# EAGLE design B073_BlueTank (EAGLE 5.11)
COMPANY: CuBeatSystems; COPYRIGHT: Shinichiro Nakamura; PROJECT_NAME: BlueTank ACB-BF592; PROJECT_NUMBER: B073; PROJECT_VERSION: 1.0.0
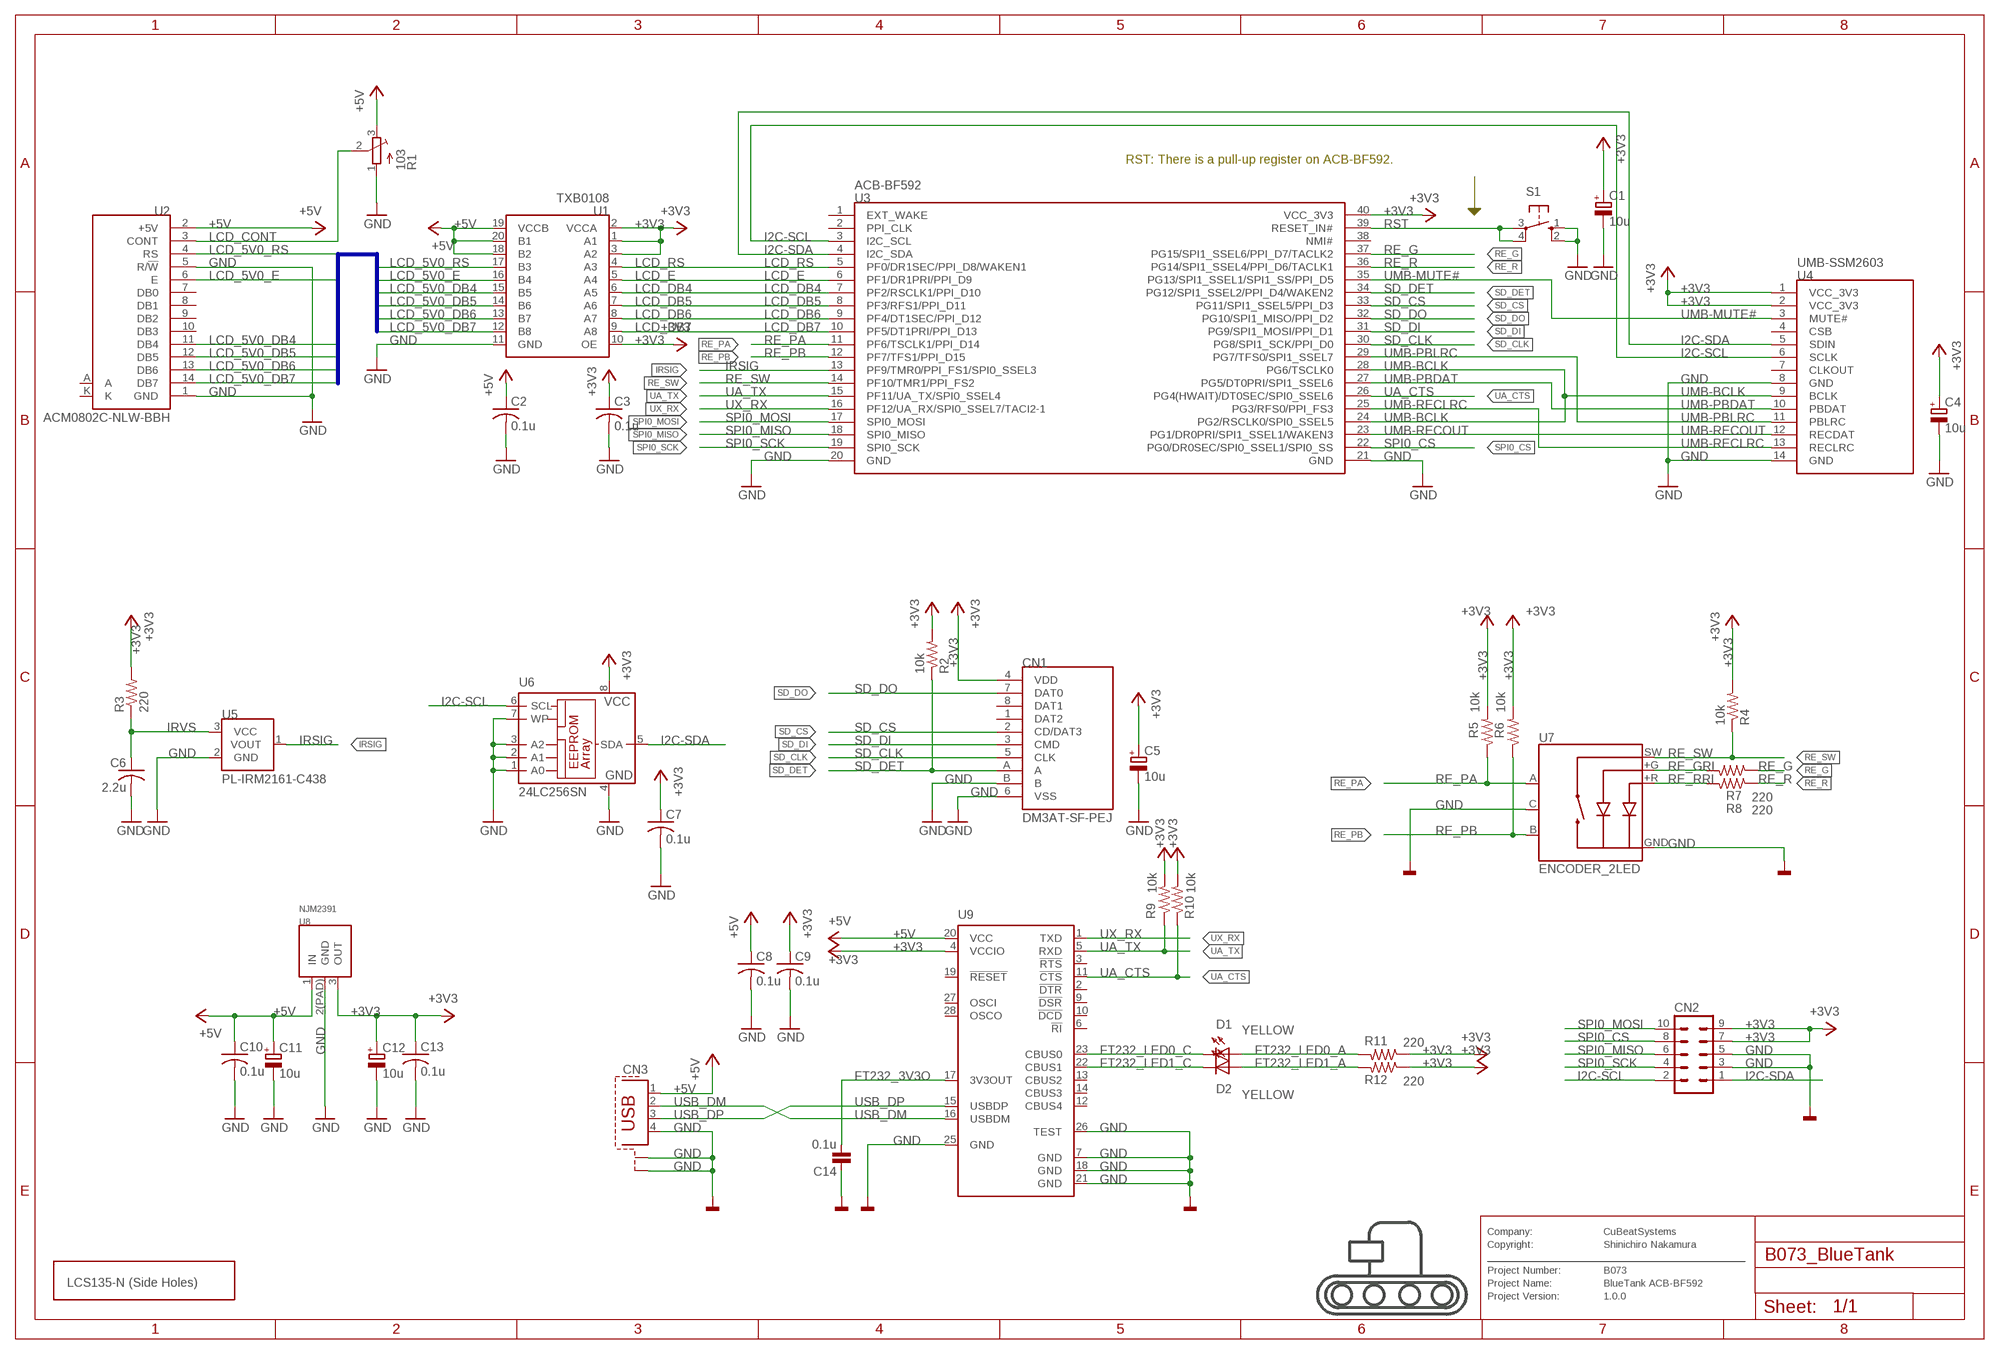
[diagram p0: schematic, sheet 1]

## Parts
C1  10u  CPOL-EUB  [PANASONIC_B]
C2  0.1u  C-USC0805  [C0805]
C3  0.1u  C-USC0805  [C0805]
C4  10u  CPOL-EUB  [PANASONIC_B]
C5  10u  CPOL-EUB  [PANASONIC_B]
C6  2.2u  C-USC0805  [C0805]
C7  0.1u  C-USC0805  [C0805]
C8  0.1u  C-USC0805  [C0805]
C9  0.1u  C-USC0805  [C0805]
C10  0.1u  C-USC0805  [C0805]
C11  10u  CPOL-EUB  [PANASONIC_B]
C12  10u  CPOL-EUB  [PANASONIC_B]
C13  0.1u  C-USC0805  [C0805]
C14  0.1u  C0603  [0603]
CN1  DM3AT-SF-PEJ  [DM3AT-SF-PEJ]
CN2  ML10L  [ML10L]
CN3  PN61729-S  [PN61729-S]
D1  YELLOW  LED_0805  [LED_0805]
D2  YELLOW  LED_0805  [LED_0805]
R1  103  TRIM_EU-SM-42/43A  [SM-42/43A]
R2  10k  R-US_M0805  [M0805]
R3  220  R-US_M0805  [M0805]
R4  10k  R-US_M0805  [M0805]
R5  10k  R-US_M0805  [M0805]
R6  10k  R-US_M0805  [M0805]
R7  220  R-US_M0805  [M0805]
R8  220  R-US_M0805  [M0805]
R9  10k  R-US_M0805  [M0805]
R10  10k  R-US_M0805  [M0805]
R11  220  R-US_M0805  [M0805]
R12  220  R-US_M0805  [M0805]
S1  10-XX  [B3F-10XX]
U1  TXB0108  [PW_R-PDSO-G20]
U2  ACM0802C-NLW-BBH  [ACM0802C-NLW-BBH]
U3  ACB-BF592  [ACB-BF592]
U4  UMB-SSM2603  [UMB-SSM2603]
U5  PL-IRM2161-C438  PL-IRM2121-A538  [PL-IRM2121-A538]
U6  24LC256SN  [SO-08]
U7  ENCODER_2LED  [ENCODER_LED_2]
U8  NJM2391  TA48M033F  [HSIP3-P-2.30B]
U9  FT232RL  [SSOP28]
V  LCS135-N-SIDE-HOLES  [LCS-135-N-SIDE-HOLES]

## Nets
+3V3: C1.+ C3.1 C4.+ C5.+ C7.1 C9.1 C12.+ C13.1 CN1.4(VDD) CN2.7 CN2.9 R2.2 R3.2 R4.2 R5.2 R6.2 R9.2 R10.2 R11.1 R12.1 U1.1(A1) U1.2(VCCA) U1.3(A2) U1.10(OE) U3.40(VCC_3V3) U4.1(VCC_3V3) U4.2(VCC_3V3) U6.8(VCC) U8.3(OUT) U9.4(VCCIO)
+5V [PWR]: C2.1 C8.1 C10.1 C11.+ CN3.1 R1.3(E) U1.18(B2) U1.19(VCCB) U1.20(B1) U2.2(+5V) U8.1(IN) U9.20(VCC)
FT232_3V3O: C14.2 U9.17(3V3OUT)
FT232_LED0_A: D1.A R11.2
FT232_LED0_C: D1.K U9.23(CBUS0)
FT232_LED1_A: D2.A R12.2
FT232_LED1_C: D2.K U9.22(CBUS1)
GND: C1.- C2.2 C3.2 C4.- C5.- C6.2 C7.2 C8.2 C9.2 C10.2 C11.- C12.- C13.2 C14.1 CN1.6(VSS) CN1.B CN2.3 CN2.5 CN3.4 CN3.S1 CN3.S2 R1.1(A) S1.1(S) S1.2(S1) U1.11(GND) U2.1(GND) U2.5(R/!W) U3.20(GND) U3.21(GND) U4.8(GND) U4.14(GND) U5.2(GND) U6.1(A0) U6.2(A1) U6.3(A2) U6.4(GND) U6.7(WP) U7.C U7.GND(-) U8.2(PAD)(GND) U9.7(GND) U9.18(GND) U9.21(GND) U9.25(GND) U9.26(TEST)
I2C-SCL: CN2.2 U3.3(I2C_SCL) U4.6(SCLK) U6.6(SCL)
I2C-SDA: CN2.1 U3.4(I2C_SDA) U4.5(SDIN) U6.5(SDA)
IRSIG: U3.13(PF9/TMR0/PPI_FS1/SPI0_SSEL3) U5.1(VOUT)
IRVS: C6.1 R3.1 U5.3(VCC)
LCD_5V0_DB4: U1.15(B5) U2.11(DB4)
LCD_5V0_DB5: U1.14(B6) U2.12(DB5)
LCD_5V0_DB6: U1.13(B7) U2.13(DB6)
LCD_5V0_DB7: U1.12(B8) U2.14(DB7)
LCD_5V0_E: U1.16(B4) U2.6(E)
LCD_5V0_RS: U1.17(B3) U2.4(RS)
LCD_CONT: R1.2(S) U2.3(CONT)
LCD_DB4: U1.6(A5) U3.7(PF2/RSCLK1/PPI_D10)
LCD_DB5: U1.7(A6) U3.8(PF3/RFS1/PPI_D11)
LCD_DB6: U1.8(A7) U3.9(PF4/DT1SEC/PPI_D12)
LCD_DB7: U1.9(A8) U3.10(PF5/DT1PRI/PPI_D13)
LCD_E: U1.5(A4) U3.6(PF1/DR1PRI/PPI_D9)
LCD_RS: U1.4(A3) U3.5(PF0/DR1SEC/PPI_D8/WAKEN1)
RE_G: R7.1 U3.37(PG15/SPI1_SSEL6/PPI_D7/TACLK2)
RE_GRI: R7.2 U7.+G
RE_PA: R5.1 U3.11(PF6/TSCLK1/PPI_D14) U7.A
RE_PB: R6.1 U3.12(PF7/TFS1/PPI_D15) U7.B
RE_R: R8.1 U3.36(PG14/SPI1_SSEL4/PPI_D6/TACLK1)
RE_RRI: R8.2 U7.+R
RE_SW: R4.1 U3.14(PF10/TMR1/PPI_FS2) U7.SW
RST: S1.3(P) S1.4(P1) U3.39(RESET_IN#)
SD_CLK: CN1.5(CLK) U3.30(PG8/SPI1_SCK/PPI_D0)
SD_CS: CN1.2(CD/DAT3) U3.33(PG11/SPI1_SSEL5/PPI_D3)
SD_DET: CN1.A R2.1 U3.34(PG12/SPI1_SSEL2/PPI_D4/WAKEN2)
SD_DI: CN1.3(CMD) U3.31(PG9/SPI1_MOSI/PPI_D1)
SD_DO: CN1.7(DAT0) U3.32(PG10/SPI1_MISO/PPI_D2)
SPI0_CS: CN2.8 U3.22(PG0/DR0SEC/SPI0_SSEL1/SPI0_SS)
SPI0_MISO: CN2.6 U3.18(SPI0_MISO)
SPI0_MOSI: CN2.10 U3.17(SPI0_MOSI)
SPI0_SCK: CN2.4 U3.19(SPI0_SCK)
UA_CTS: R10.1 U3.26(PG4(HWAIT)/DT0SEC/SPI0_SSEL6) U9.11(!CTS)
UA_TX: R9.1 U3.15(PF11/UA_TX/SPI0_SSEL4) U9.5(RXD)
UMB-BCLK: U3.24(PG2/RSCLK0/SPI0_SSEL5) U3.28(PG6/TSCLK0) U4.9(BCLK)
UMB-MUTE#: U3.35(PG13/SPI1_SSEL1/SPI1_SS/PPI_D5) U4.3(MUTE#)
UMB-PBDAT: U3.27(PG5/DT0PRI/SPI1_SSEL6) U4.10(PBDAT)
UMB-PBLRC: U3.29(PG7/TFS0/SPI1_SSEL7) U4.11(PBLRC)
UMB-RECLRC: U3.25(PG3/RFS0/PPI_FS3) U4.13(RECLRC)
UMB-RECOUT: U3.23(PG1/DR0PRI/SPI1_SSEL1/WAKEN3) U4.12(RECDAT)
USB_DM: CN3.2 U9.16(USBDM)
USB_DP: CN3.3 U9.15(USBDP)
UX_RX: U3.16(PF12/UA_RX/SPI0_SSEL7/TACI2-1) U9.1(TXD)
Unconnected: CN1.1(DAT2) CN1.8(DAT1) U2.7(DB0) U2.8(DB1) U2.9(DB2) U2.10(DB3) U2.A U2.K U3.1(EXT_WAKE) U3.2(PPI_CLK) U3.38(NMI#) U4.4(CSB) U4.7(CLKOUT) U9.2(!DTR) U9.3(!RTS) U9.6(!RI) U9.9(!DSR) U9.10(!DCD) U9.12(CBUS4) U9.13(CBUS2) U9.14(CBUS3) U9.19(!RESET) U9.27(OSCI) U9.28(OSCO)

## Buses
LCD_5V0_RS,LCD_5V0_E,LCD_5V0_DB[4..7]

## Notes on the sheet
- RST: There is a pull-up register on ACB-BF592.
- Company:
- Copyright:
- Project Number:
- Project Name:
- Project Version:

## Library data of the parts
C1 C4 C5 C11 C12 = rcl:CPOL-EU: POLARIZED CAPACITOR, European symbol
C2 C3 C6-C10 C13 = rcl:C-US: CAPACITOR, American symbol
C14 = mbed:C
CN1 = cbs-hirose:DM3AT-SF-PEJ
CN2 = con-harting-ml:ML10: HARTING; OC_FARNELL: unknown; OC_NEWARK: unknown
CN3 = con-berg:PN61729-S: BERG USB connector; OC_FARNELL: unknown; OC_NEWARK: unknown
D1 D2 = mbed:LED
R1 = pot:TRIM_EU-: POTENTIOMETER
R2-R12 = rcl:R-US_: RESISTOR, American symbol
S1 = switch-omron:10-XX: OMRON SWITCH; MPN: B3F-1000; OC_FARNELL: 176432; OC_NEWARK: 36M3542
U1 = cbs-texas:TXB0108
U2 = cbs-az_displays:ACM0802C-NLW-BBH
U3 = KanekoSystem:ACB-BF592: Kaneko System ACB-BF592
U4 = KanekoSystem:UMB-SSM2603
U5 = cbs-para_light:PL-IRM2121-A538
U6 = microchip:24*: Serial EEPROM I2C; MF: MICROCHIP; MPN: 24LC256-I/SN; OC_FARNELL: 9757996; OC_NEWARK: 27C9144
U7 = SparkFun:ENCODER_2LED: Illuminated Rotary Encoder w/ 2 LEDs
U8 = cbs-toshiba:TA48M033F
U9 = ftdichip:FT232R: Source: http://www.ftdichip.com/Documents/DataSheets/DS_FT232R_v104.pdf; MPN: FT232RL; OC_FARNELL: 1146032; OC_NEWARK: 91K9918
V = Board-Outline-For-BlueTank:LCS135-N-SIDE-HOLES

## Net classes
0 default: width 0.203 mm, drill 0.203 mm, clearance 0.203 mm
1 PWR: width 0.203 mm, drill 0.203 mm, clearance 0.203 mm
2 GND: width 0.203 mm, drill 0.203 mm, clearance 0.203 mm

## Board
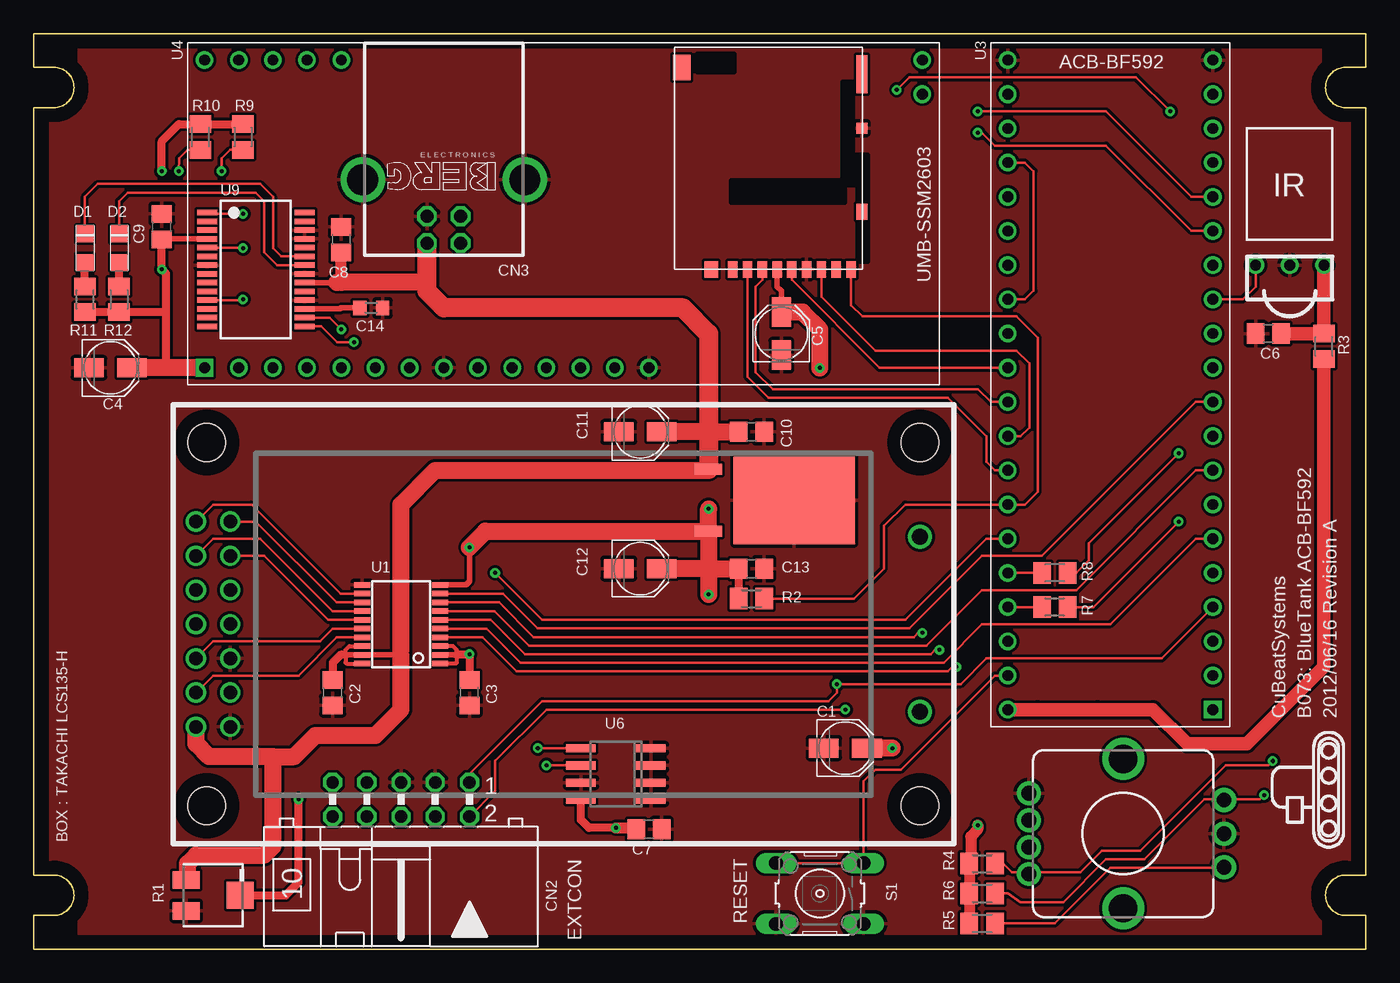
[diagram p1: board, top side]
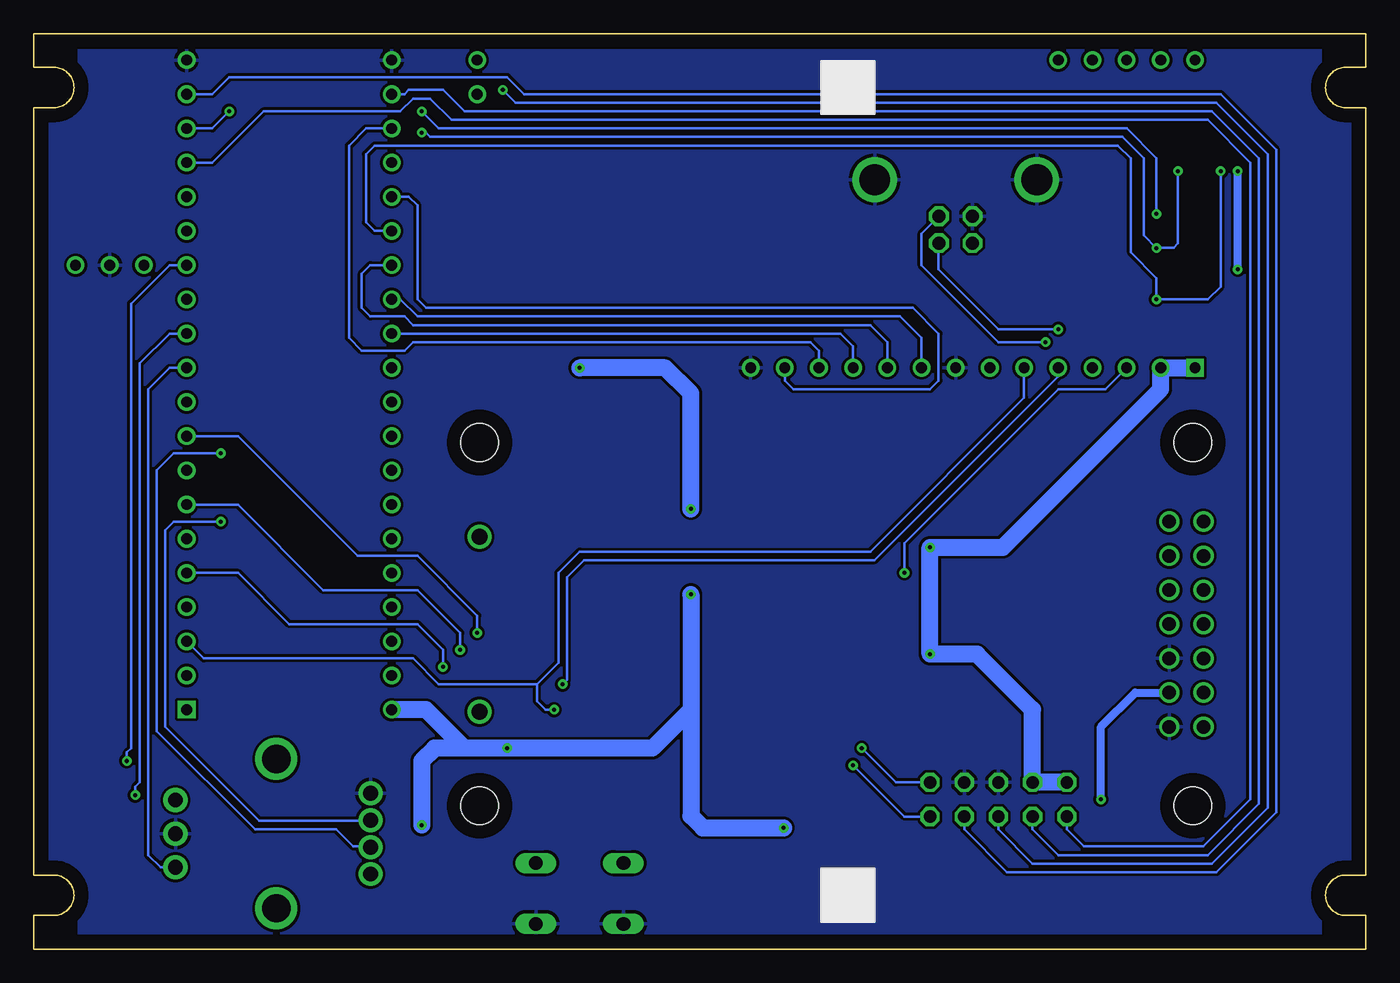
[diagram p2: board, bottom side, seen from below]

Size 99 x 68 mm. Coordinates in mm from the lower left corner, seen from the top.
Copper layers (1*16): Top 0.035mm / dielectric 1.5mm / Bottom 0.035mm
Design rules "default *": minimum track width 8mil, minimum drill 0.3mm, track to track 8mil, track to pad 8mil, pad to pad 8mil, via to via 8mil, smd to smd 8mil, copper to edge 40mil, drill to drill 8mil, minimum pad ring 10mil, minimum via ring 8mil, stop-mask expansion 4mil, vias tented up to drill 0mil, thermal gap 10mil

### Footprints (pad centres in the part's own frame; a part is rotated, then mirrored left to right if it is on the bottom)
PANASONIC_B = smd 2.2 x 1.4: + 1.6,0; - -1.6,0
C0805 = smd 1.3 x 1.5: 1 -0.95,0; 2 0.95,0
0603 = smd 1 x 1.1: 1 -0.85,0; 2 0.85,0
DM3AT-SF-PEJ = smd 0.7 x 1.2: 1 2.03,7.62; 2 0.93,7.62; 3 -0.17,7.62; 4 -1.27,7.62; 5 -2.37,7.62; 6 -3.47,7.62; 7 -4.57,7.62; 8 -5.67,7.62; A -6.77,7.62 | smd 0.8 x 0.8: B -7.57,-2.88 | smd 0.8 x 1.2: PAD1 -7.57,3.32 | smd 0.8 x 2.8: PAD2 -7.57,-6.88 | smd 1.3 x 1.9: PAD3 5.83,-7.38 | smd 1 x 1.2: PAD4 3.63,7.62
ML10L = drill 0.914 octagon: 1 -5.08,-1.27; 2 -5.08,1.27; 3 -2.54,-1.27; 4 -2.54,1.27; 5 0,-1.27; 6 0,1.27; 7 2.54,-1.27; 8 2.54,1.27; 9 5.08,-1.27; 10 5.08,1.27
PN61729-S = drill 0.95 octagon: 1 1.25,4.71; 2 -1.25,4.71; 3 -1.25,2.71; 4 1.25,2.71 | drill 2.3 pad 2.9 round: S1 -6.02,0; S2 6.02,0
LED_0805 = smd 1.2 x 1.25: A 1.05,0; K -1.05,0
SM-42/43A = smd 2 x 1.3: 1 2,1.15; 3 2,-1.15 | smd 2 x 2: 2 -2,0
M0805 = smd 1.3 x 1.6: 1 -0.95,0; 2 0.95,0
B3F-10XX = drill 1.016 long: 1 -3.251,2.261; 2 3.251,2.261; 3 -3.251,-2.261; 4 3.251,-2.261
PW_R-PDSO-G20 = smd 0.4 x 1.2: 1 -2.925,-2.9; 2 -2.275,-2.9; 3 -1.625,-2.9; 4 -0.975,-2.9; 5 -0.325,-2.9; 6 0.325,-2.9; 7 0.975,-2.9; 8 1.625,-2.9; 9 2.275,-2.9; 10 2.925,-2.9; 11 2.925,2.9; 12 2.275,2.9; 13 1.625,2.9; 14 0.975,2.9; 15 0.325,2.9; 16 -0.325,2.9; 17 -0.975,2.9; 18 -1.625,2.9; 19 -2.275,2.9; 20 -2.925,2.9
ACM0802C-NLW-BBH = drill 1 round: 1 -24.76,-7.62; 2 -27.3,-7.62; 3 -24.76,-5.08; 4 -27.3,-5.08; 5 -24.76,-2.54; 6 -27.3,-2.54; 7 -24.76,0; 8 -27.3,0; 9 -24.76,2.54; 10 -27.3,2.54; 11 -24.76,5.08; 12 -27.3,5.08; 13 -24.76,7.62; 14 -27.3,7.62 | drill 1.2 round: A 26.5,6.5; K 26.5,-6.5 | hole 2.8: -26.5,13.5; 26.5,13.5; -26.5,-13.5; 26.5,-13.5
ACB-BF592 = drill 0.8 square: 1 0,0 | drill 0.8 round: 2 2.54,0; 3 5.08,0; 4 7.62,0; 5 10.16,0; 6 12.7,0; 7 15.24,0; 8 17.78,0; 9 20.32,0; 10 22.86,0; 11 25.4,0; 12 27.94,0; 13 30.48,0; 14 33.02,0; 15 35.56,0; 16 38.1,0; 17 40.64,0; 18 43.18,0; 19 45.72,0; 20 48.26,0; 21 48.26,15.24; 22 45.72,15.24; 23 43.18,15.24; 24 40.64,15.24; 25 38.1,15.24; 26 35.56,15.24; 27 33.02,15.24; 28 30.48,15.24; 29 27.94,15.24; 30 25.4,15.24; 31 22.86,15.24; 32 20.32,15.24; 33 17.78,15.24; 34 15.24,15.24; 35 12.7,15.24; 36 10.16,15.24; 37 7.62,15.24; 38 5.08,15.24; 39 2.54,15.24; 40 0,15.24
UMB-SSM2603 = drill 0.8 square: 1 0,0 | drill 0.8 round: 2 2.54,0; 3 5.08,0; 4 7.62,0; 5 10.16,0; 6 12.7,0; 7 15.24,0; 8 17.78,0; 9 20.32,0; 10 22.86,0; 11 25.4,0; 12 27.94,0; 13 30.48,0; 14 33.02,0; NC@1 0,22.86; NC@2 2.54,22.86; NC@3 5.08,22.86; NC@4 7.62,22.86; NC@5 10.16,22.86; NC@6 53.34,22.86; NC@7 53.34,20.32
PL-IRM2121-A538 = drill 0.8 round: 1 -2.54,1.27; 2 0,1.27; 3 2.54,1.27
SO-08 = smd 0.6 x 2.2: 1 -1.905,-2.6; 2 -0.635,-2.6; 3 0.635,-2.6; 4 1.905,-2.6; 5 1.905,2.6; 6 0.635,2.6; 7 -0.635,2.6; 8 -1.905,2.6
ENCODER_LED_2 = drill 1.1 pad 1.778 round: +G 1,7; +R -1,7; GND 3,7; SW -3,7 | drill 1.1 pad 1.8 round: A -2.5,-7.5; B 2.5,-7.5; C 0,-7.5 | drill 2.1 round: P$1 -5.55,0; P$2 5.55,0
HSIP3-P-2.30B = smd 0.8 x 2: 1 -2.3,0; 3 2.3,0 | smd 6.5 x 9: 2(PAD) 0,6.35
SSOP28 = smd 0.4 x 1.5: 1 -4.225,-3.625; 2 -3.575,-3.625; 3 -2.925,-3.625; 4 -2.275,-3.625; 5 -1.625,-3.625; 6 -0.975,-3.625; 7 -0.325,-3.625; 8 0.325,-3.625; 9 0.975,-3.625; 10 1.625,-3.625; 11 2.275,-3.625; 12 2.925,-3.625; 13 3.575,-3.625; 14 4.225,-3.625; 15 4.225,3.625; 16 3.575,3.625; 17 2.925,3.625; 18 2.275,3.625; 19 1.625,3.625; 20 0.975,3.625; 21 0.325,3.625; 22 -0.325,3.625; 23 -0.975,3.625; 24 -1.625,3.625; 25 -2.275,3.625; 26 -2.925,3.625; 27 -3.575,3.625; 28 -4.225,3.625

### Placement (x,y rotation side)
C1  60.33,14.92 0 top
C2  22.23,19.05 270 top
C3  32.38,19.05 270 top
C4  5.71,43.18 0 top
C5  55.56,45.72 90 top
C6  91.76,45.72 180 top
C7  45.72,8.89 0 top
C8  22.86,52.7 90 top
C9  9.53,53.66 90 top
C10  53.34,38.42 0 top
C11  45.09,38.42 0 top
C12  45.09,28.26 0 top
C13  53.34,28.26 0 top
C14  25.08,47.62 180 top
CN1  53.98,58.1 180 top
CN2  27.3,11.11 180 top
CN3  30.48,57.15 180 top
D1  3.81,52.07 270 top
D2  6.35,52.07 270 top
R1  13.34,3.99 180 top
R2  53.34,26.04 180 top
R3  95.89,44.77 270 top
R4  70.48,6.35 180 top
R5  70.48,1.91 180 top
R6  70.48,4.13 180 top
R7  75.88,25.4 0 top
R8  75.88,27.94 0 top
R9  15.56,60.33 90 top
R10  12.38,60.33 90 top
R11  3.81,48.26 90 top
R12  6.35,48.26 90 top
S1  58.42,4.13 180 top
U1  27.3,24.13 90 top
U2  39.37,24.13 0 top
U3  87.63,17.78 90 top
U4  12.7,43.18 0 top
U5  93.34,49.53 0 top
U6  43.27,13 90 top
U7  80.96,8.57 90 top
U8  50.16,33.34 270 top
U9  16.51,50.48 270 top
V  0,0 0 top

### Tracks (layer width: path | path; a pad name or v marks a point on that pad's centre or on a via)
+3V3  (via drill 0.3)
  Top 0.305: U1.3 31.15,22.5 31.43,22.23 31.43,21.86 31.43,21.27 31.36,21.2 U1.1
  Top 0.406: CN1.4 55.24,49.21 55.56,48.9 C5.+ | 31.43,21.86 U1.2 | v32.38,21.91 32.33,21.86 | U1.10 32.13,27.05 32.38,27.3 v32.38,29.84 | U9.4 9.57,52.76 C9.1
  Top 0.61: v32.38,21.91 C3.1 | 32.33,21.86 31.43,21.86 | C4.+ 9.84,43.19 9.84,47.31 | C13.1 R2.2 | R9.2 R10.2 10.79,61.27 9.53,60.01 v9.53,57.78 | 9.84,47.31 9.84,50.16 v9.53,50.48 C9.1 | v43.27,9 41.27,9 40.67,9.6 U6.8 | 9.84,47.31 R12.1 R11.1
  Top 0.813: v70.17,9.21 70.17,8.89 69.64,8.36 69.64,6.45 R4.2 R6.2 R5.2 | v43.27,9 44.66,9 C7.1
  Top 1.016: U3.40 74.61,17.78 79.06,17.78 83.19,17.78 85.72,15.24 90.17,15.24 95.89,20.95 R3.2
  Top 1.27: U8.3 50.16,28.26 | 50.16,28.26 C13.1 | 50.16,28.26 C12.+ | U8.3 33.58,31.04 v32.38,29.84 | U4.1 C4.+ | U8.3 v50.16,26.35 | C1.+ 62.22,14.91 v63.82,14.92 | U8.3 v50.16,32.7 | v58.42,43.18 58.42,46.04 57.15,47.31 55.58,47.31 C5.+
  Bottom 0.61: v9.53,50.48 v9.53,57.78
  Bottom 1.27: U4.1 U4.2 15.24,41.59 26.99,29.84 v32.38,29.84 v32.38,21.91 28.89,21.91 24.77,17.78 CN2.7 CN2.9 | v50.16,26.35 50.16,17.78 | 50.16,17.78 53.02,14.92 v63.82,14.92 66.99,14.92 | 66.99,14.92 69.85,17.78 U3.40 | v50.16,32.7 50.16,41.27 52.07,43.18 v58.42,43.18 | 66.99,14.92 69.22,14.92 70.17,13.97 v70.17,9.21 | 50.16,17.78 50.16,9.89 49.27,9 v43.27,9
+5V
  Top 0.305: U1.18 23.46,22.5 23.18,22.23 23.18,21.86 23.18,21.27 23.25,21.2 U1.20
  Top 0.406: 27.3,22.23 27.25,21.86 U1.19 23.18,21.86 | U9.20 22.52,49.51 22.54,49.53
  Top 0.61: 23.18,21.86 22.81,21.86 22.23,21.27 C2.1
  Top 0.813: 22.86,49.53 C8.1
  Top 1.27: C10.1 50.16,38.42 C11.+ | 50.16,45.72 50.16,35.56 29.84,35.56 27.3,33.02 27.3,22.23 | U2.2 12.07,15.23 13.02,14.29 17.78,14.29 | 17.78,14.29 19.37,14.29 20.95,15.88 25.4,15.88 27.3,17.78 27.3,21.8 27.25,21.86 | 29.23,48.88 29.23,49.51 29.21,49.53 22.86,49.53 22.54,49.53 | 17.78,14.29 17.78,7.62 17.14,6.99 12.06,6.99 11.43,6.35 11.43,5.74 R1.3
  Top 1.422: CN3.1 29.23,48.88 30.48,47.62 48.26,47.62 50.16,45.72 50.16,38.42 U8.1
FT232_3V3O
  Top 0.406: U9.17 22.79,47.56 22.86,47.62 C14.2
FT232_LED0_A
  Top 0.61: R11.2 D1.A
FT232_LED0_C
  Top 0.203: D1.K 3.81,55.88 4.76,56.83 16.83,56.83 17.78,55.88 17.78,52.07 18.39,51.46 U9.23
FT232_LED1_A
  Top 0.61: R12.2 D2.A
FT232_LED1_C
  Top 0.203: U9.22 18.09,50.81 17.14,51.75 17.14,55.56 16.51,56.2 6.99,56.2 6.35,55.56 D2.K
GND
  pour Top (isolate 0.203): 3.37,67 3.37,64 arc-90 1,61.95 1,6.05 arc-90 3.37,4 3.37,1 95.64,1 95.64,4 arc-90 98,6.05 98,61.95 arc-90 95.64,64 95.64,67
  pour Bottom (isolate 0.203): 3.37,67 3.37,64 arc-90 1,61.95 1,6.05 arc-90 3.37,4 3.37,1 95.64,1 95.64,4 arc-90 98,6.05 98,61.95 arc-90 95.64,64 95.64,67
I2C-SCL  (via drill 0.3)
  Top 0.203: v60.33,17.78 38.1,17.78 34.29,13.97 34.29,11.75 CN2.2 | U6.6 38.12,13.63 v38.1,13.65
  Bottom 0.203: U4.6 25.4,40.96 36.83,29.53 58.42,29.53 60.01,27.94 60.01,21.27 61.59,19.68 | 61.59,19.68 68.9,19.68 70.8,21.59 86.36,21.59 U3.3 | v60.33,17.78 60.96,17.78 61.59,18.41 61.59,19.68 | v38.1,13.65 34.29,9.84 CN2.2
I2C-SDA  (via drill 0.3)
  Top 0.203: U3.4 83.82,21.59 70.8,21.59 68.9,19.68 v59.69,19.68 59.69,19.05 59.05,18.41 37.78,18.41 32.38,13.02 CN2.1 | U6.5 38.12,14.9 v37.47,14.92
  Bottom 0.203: U4.5 22.86,42.55 36.51,28.89 58.1,28.89 59.37,27.62 59.37,20 v59.69,19.68 | v37.47,14.92 34.92,12.38 CN2.1
IRSIG
  Top 0.203: U3.13 89.85,48.26 90.81,49.21 U5.1
IRVS
  Top 1.016: C6.1 R3.1 U5.3
LCD_5V0_DB4
  Top 0.203: U2.11 17.14,29.21 21.9,24.45 U1.15
LCD_5V0_DB5
  Top 0.203: U2.12 13.34,30.48 16.83,30.48 22.2,25.11 U1.14
LCD_5V0_DB6
  Top 0.203: U2.13 16.51,31.75 22.5,25.75 U1.13
LCD_5V0_DB7
  Top 0.203: U2.14 13.34,33.02 16.19,33.02 22.81,26.41 U1.12
LCD_5V0_E
  Top 0.203: U2.6 13.34,22.86 21.27,22.86 22.22,23.8 U1.16
LCD_5V0_RS
  Top 0.203: U2.4 13.34,20.32 19.68,20.32 22.52,23.16 U1.17
LCD_CONT  (via drill 0.3)
  Top 0.61: v19.68,11.11 19.68,4.95 18.73,3.99 R1.2
  Bottom 0.61: U2.3 17.14,19.05 19.68,16.51 v19.68,11.11
LCD_DB4  (via drill 0.3)
  Top 0.203: U1.6 33.97,24.45 36.51,21.91 66.67,21.91 66.99,22.23 v67.31,22.23
  Bottom 0.203: v67.31,22.23 67.31,23.5 70.48,26.67 77.47,26.67 83.82,33.02 U3.7
LCD_DB5
  Top 0.203: U1.7 34.27,25.11 36.83,22.54 66.36,22.54 70.48,26.67 77.47,26.67 86.36,35.56 U3.8
LCD_DB6  (via drill 0.3)
  Top 0.203: U1.8 34.57,25.75 37.15,23.18 65.41,23.18 65.72,23.5 v66.04,23.5
  Bottom 0.203: v66.04,23.5 66.04,24.77 70.48,29.21 74.93,29.21 83.82,38.1 U3.9
LCD_DB7
  Top 0.203: U1.9 34.87,26.41 37.47,23.81 65.09,23.81 70.48,29.21 74.93,29.21 86.36,40.64 U3.10
LCD_E
  Top 0.203: U1.5 33.66,23.8 36.2,21.27 67.63,21.27 70.48,24.13 80.01,24.13 86.36,30.48 U3.6
LCD_RS  (via drill 0.3)
  Top 0.203: U1.4 33.36,23.16 35.88,20.64 67.94,20.64 68.26,20.95 v68.58,20.95
  Bottom 0.203: v68.58,20.95 68.58,22.23 70.48,24.13 80.01,24.13 83.82,27.94 U3.5
RE_G
  Top 0.203: U3.37 R7.1
RE_GRI  (via drill 0.3)
  Top 0.203: v85.09,31.75 78.74,25.4 R7.2
  Bottom 0.203: v85.09,31.75 88.58,31.75 89.22,31.11 89.22,16.51 82.23,9.53 74.01,9.53 U7.+G
RE_PA
  Top 0.203: U7.A 88.42,6.03 80.01,6.03 75.88,1.91 R5.1
  Bottom 0.203: U7.A 89.58,6.07 90.49,6.99 90.49,41.59 88.9,43.18 U3.11
RE_PB  (via drill 0.3)
  Top 0.203: 88.42,11.11 87,11.11 82.55,6.67 79.69,6.67 76.52,3.49 73.34,3.49 72.39,4.13 R6.1 | 88.42,11.11 U7.B | 88.42,11.11 91.12,11.11 v91.44,11.43
  Bottom 0.203: v91.44,11.43 91.44,12.06 91.12,12.38 91.12,43.5 88.9,45.72 U3.12
RE_R
  Top 0.203: U3.36 R8.1
RE_RRI  (via drill 0.3)
  Top 0.203: v85.09,36.83 78.42,30.16 78.42,28.89 77.47,27.94 R8.2
  Bottom 0.203: v85.09,36.83 88.58,36.83 89.85,35.56 89.85,16.19 82.55,8.89 76.52,8.89 75.25,7.62 74.01,7.62 U7.+R
RE_SW  (via drill 0.3)
  Top 0.203: 73.82,5.71 72.71,5.71 72.07,6.35 R4.1 | 73.82,5.71 U7.SW | 73.82,5.71 77.79,5.71 79.38,7.3 82.23,7.3 88.58,13.65 91.76,13.65 v92.08,13.97
  Bottom 0.203: v92.08,13.97 92.08,14.61 91.76,14.92 91.76,47.94 88.9,50.8 U3.14
RST
  Top 0.203: S1.4 S1.3 61.67,12.46 62.55,13.34 64.45,13.34 71.44,20.32 U3.39
SD_CLK
  Top 0.203: U3.30 62.87,43.18 56.34,49.7 CN1.5
SD_CS
  Top 0.203: CN1.2 53.05,42.52 54.61,40.96 67.94,40.96 70.8,38.1 70.8,36.2 71.44,35.56 U3.33
SD_DET
  Top 0.203: CN1.A 60.74,47.84 61.59,46.99 73.03,46.99 74.61,45.4 74.61,33.97 73.66,33.02 U3.34 64.77,33.02 63.18,31.43 63.18,28.26 60.96,26.04 R2.1
SD_DI
  Top 0.203: U3.31 71.12,40.64 70.17,41.59 54.93,41.59 53.66,42.86 53.66,49.21 54.15,49.7 CN1.3
SD_DO
  Top 0.203: CN1.7 58.55,48.45 62.55,44.45 73.03,44.45 73.98,43.5 73.98,38.73 73.34,38.1 U3.32
SPI0_CS
  Bottom 0.203: U3.22 71.44,63.5 71.12,63.82 68.58,63.82 66.99,62.23 11.43,62.23 7.94,58.74 7.94,10.79 11.75,6.99 22.86,6.99 24.77,8.89 CN2.8
SPI0_MISO  (via drill 0.3)
  Top 0.203: v84.45,62.23 81.92,64.77 65.09,64.77 v64.14,63.82
  Bottom 0.203: U3.18 85.72,60.96 v84.45,62.23 | v64.14,63.82 63.18,62.87 11.11,62.87 7.3,59.05 7.3,10.48 11.43,6.35 24.77,6.35 27.3,8.89 CN2.6
SPI0_MOSI
  Bottom 0.203: U3.17 85.72,58.42 81.92,62.23 71.75,62.23 70.8,63.18 69.53,63.18 67.94,61.59 11.75,61.59 8.57,58.42 8.57,11.11 12.06,7.62 20.95,7.62 22.23,8.89 CN2.10
SPI0_SCK
  Bottom 0.203: U3.19 85.72,63.5 84.45,64.77 63.82,64.77 62.55,63.5 10.79,63.5 6.67,59.37 6.67,10.16 11.11,5.71 26.67,5.71 29.84,8.89 CN2.4
UA_CTS  (via drill 0.3)
  Top 0.203: U9.11 15.51,48.21 v15.56,48.26 | R10.1 11.43,59.37 10.8,58.74 v10.79,57.78
  Bottom 0.203: U3.26 73.66,53.34 74.3,53.98 74.3,59.05 73.66,59.69 18.41,59.69 17.46,58.74 17.46,51.75 15.56,49.85 v15.56,48.26 11.75,48.26 10.79,49.21 v10.79,57.78
UA_TX  (via drill 0.3)
  Top 0.203: U9.5 15.52,52.11 v15.56,52.07 | R9.1 14.61,59.37 13.97,58.74 v13.97,57.78 | v70.17,60.64 70.48,60.64 71.44,59.69 79.69,59.69 86.04,53.34 U3.15
  Bottom 0.203: v13.97,57.78 13.97,52.42 14.29,52.11 15.52,52.11 v15.56,52.07 16.51,53.02 16.51,58.74 18.1,60.33 69.53,60.33 69.85,60.64 v70.17,60.64
UMB-BCLK
  Top 0.203: U3.24 73.66,58.42 74.3,57.78 74.3,48.9 73.66,48.26 U3.28
  Bottom 0.203: U4.9 33.02,45.4 34.61,46.99 70.48,46.99 71.75,48.26 U3.28
UMB-MUTE#  (via drill 0.3)
  Top 0.203: U3.35 70.8,30.48 64.77,24.45 37.78,24.45 v34.29,27.94
  Bottom 0.203: v34.29,27.94 34.29,30.16 22.86,41.59 19.37,41.59 U4.3
UMB-PBDAT
  Bottom 0.203: U4.10 35.56,45.09 36.83,46.35 70.8,46.35 71.44,46.99 73.98,46.99 74.61,47.62 74.61,50.16 73.98,50.8 U3.27
UMB-PBLRC
  Bottom 0.203: U4.11 38.1,44.77 39.05,45.72 U3.29
UMB-RECLRC
  Bottom 0.203: U3.25 71.12,55.88 70.48,55.24 70.48,48.26 69.85,47.62 33.66,47.62 31.75,45.72 31.75,42.23 32.38,41.59 42.55,41.59 43.18,42.23 U4.13
UMB-RECOUT
  Bottom 0.203: U4.12 40.64,44.45 41.27,45.09 70.8,45.09 71.44,44.45 74.61,44.45 75.56,45.4 75.56,59.69 74.3,60.96 U3.23
USB_DM  (via drill 0.3)
  Top 0.203: U9.16 21.99,46.91 v22.86,46.04
  Bottom 0.203: v22.86,46.04 27.3,46.04 31.75,50.48 31.75,52.42 CN3.2
USB_DP  (via drill 0.3)
  Top 0.203: U9.15 21.37,46.26 22.54,45.09 v23.81,45.09
  Bottom 0.203: v23.81,45.09 27.3,45.09 33.02,50.8 33.02,53.15 CN3.3
UX_RX  (via drill 0.3)
  Top 0.203: v15.56,54.61 12.98,54.61 U9.1 | v70.17,62.23 79.69,62.23 86.04,55.88 U3.16
  Bottom 0.203: v15.56,54.61 15.56,58.74 17.78,60.96 68.9,60.96 v70.17,62.23

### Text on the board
Top: Top
Bottom: Bottom
Pads: Pads
Vias: Vias
Dimension: Dimension
tPlace: IR | tPlace
tNames: ACB-BF592 | tNames | UMB-SSM2603 | CuBeatSystems | B073: BlueTank ACB-BF592 | 2012/06/16 Revision A | BOX : TAKACHI LCS135-H | EXTCON | RESET
bNames: bNames
bValues: bPlace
